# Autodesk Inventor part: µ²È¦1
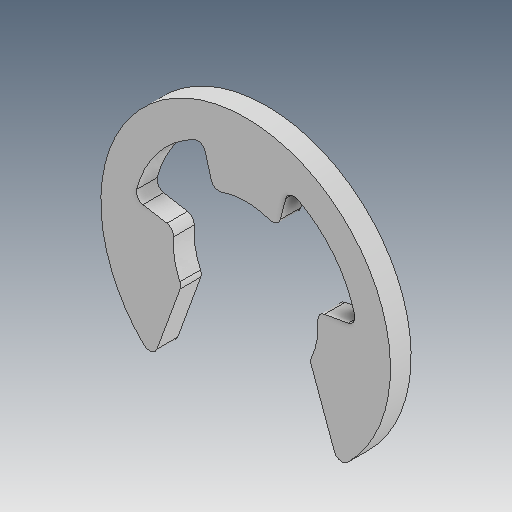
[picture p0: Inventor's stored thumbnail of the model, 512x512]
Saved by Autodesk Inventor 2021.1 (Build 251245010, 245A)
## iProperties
Created: 2013-04
Part Number: µ²È¦1
Material: Ogólny
Document SubType Name: Modeling
Designer: user
Density: 1 g/cm^3
Appearance: Domyślna
Author: user
Revision Number: ÈÎºÎ
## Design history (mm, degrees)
feature "À­Éì1"
node "Bryła1"
